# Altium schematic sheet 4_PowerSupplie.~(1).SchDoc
size 414 x 293 mm; SheetNumber: 4; SheetTotal: 4; PageSetup: Record=PageOptionsZCenterHorizontal=TrueZCenterVertical=TrueZPrintScale=1.00ZXCorrection=0.00ZYCorrection=0.00ZPrintKind=1ZBorderSize=5000000ZLeftOffset=0ZBottomOffset=0ZOrientation=2ZPaperLength=1000ZPaperWidth=1000ZScale=100ZPaperSource=7ZPrintQuality=-4ZMediaType=1ZDitherType=10ZPaperKind=A3ZPrintScaleMode=0; Razrabotal: {Разработал}; Proveril: {Проверил}; Tkontr: {Т.контр.}; Nkontr: {Н.контр.}; Ytverdil: {Утвердил}; Nazvanie1: {Название1}; Nazvanie2: {Название2}; Oboznachenie: {Обозначение}
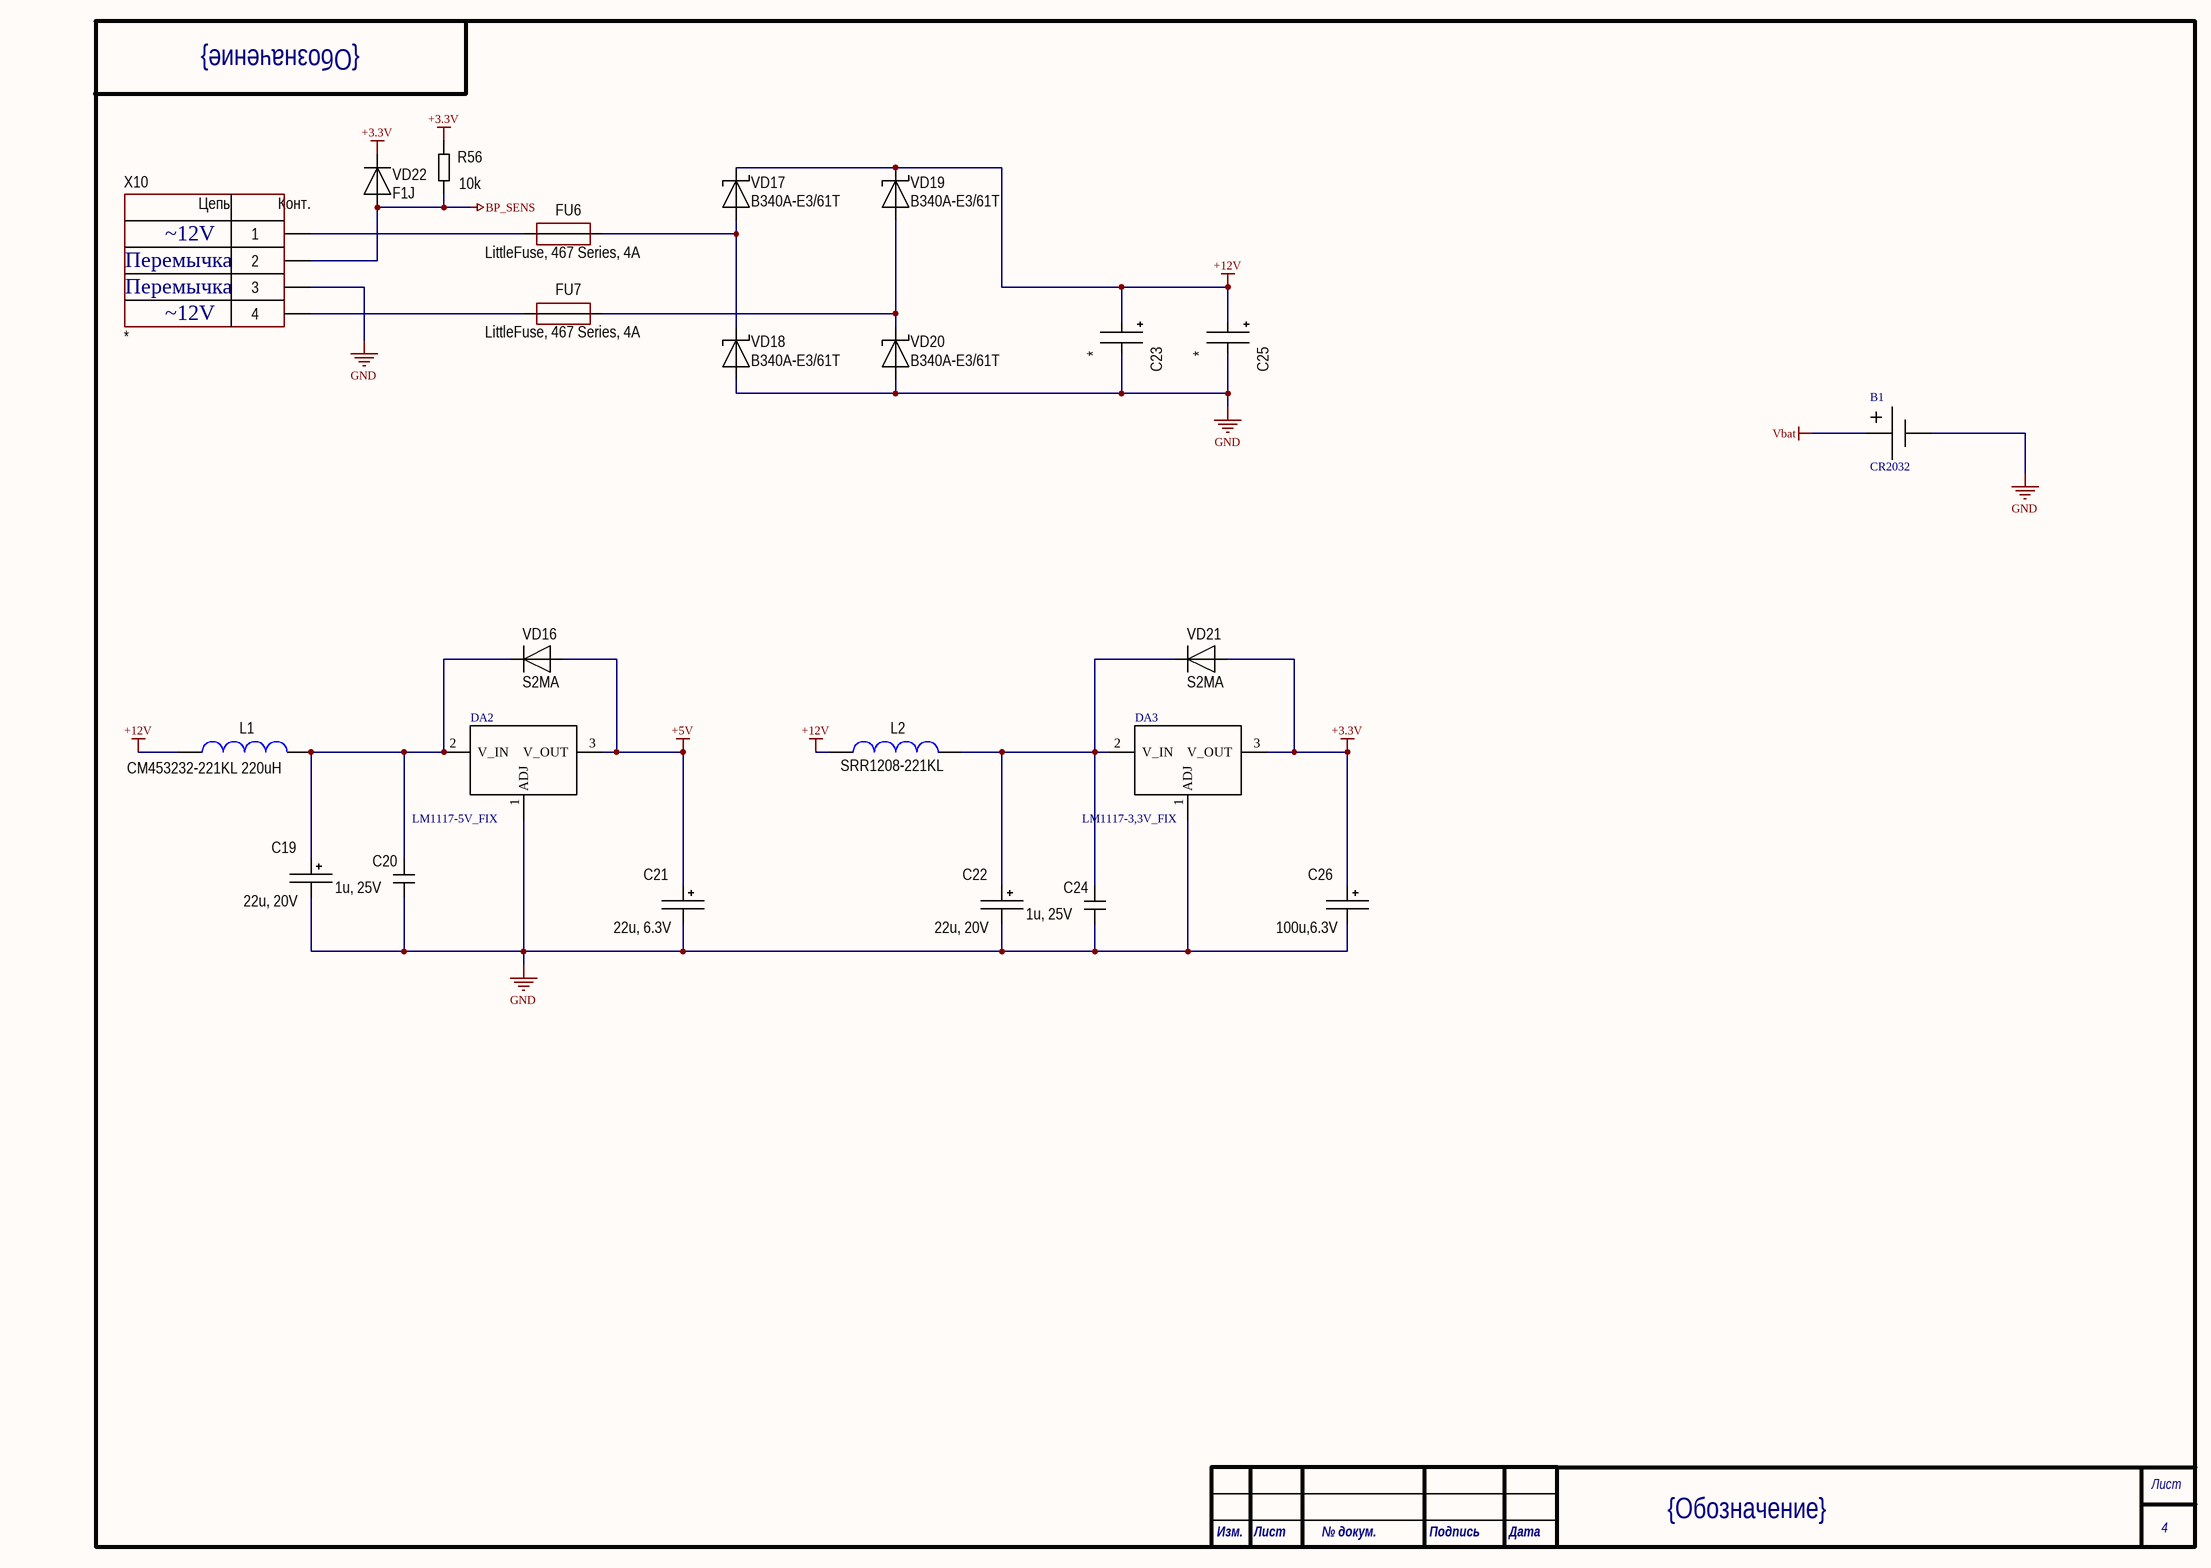
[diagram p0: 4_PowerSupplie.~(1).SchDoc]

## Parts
B1  CR2032  [CR2032]
C19  22u, 20V  [TANTAL_B]
C20  1u, 25V  [CH0805C]
C21  22u, 6.3V  [TANTAL_B]
C22  22u, 20V  [TANTAL_B]
C23  *  [D10C4.4H10]
C24  1u, 25V  [CH0805C]
C25  *  [D10C4.4H10]
C26  100u,6.3V  [TANTAL_B]
DA2  LM1117-5V_FIX  [SOT223_123]
DA3  LM1117-3,3V_FIX  [SOT223_123]
FU6  LittleFuse, 467 Series, 4A  [CH0603F]
FU7  LittleFuse, 467 Series, 4A  [CH0603F]
L1  CM453232-221KL 220uH  [IND:1812]
L2  SRR1208-221KL  [IND: SRR1208]
R56  10k  [CH0805R]
VD16  S2MA  [SMA]
VD17  B340A-E3/61T  [SMA]
VD18  B340A-E3/61T  [SMA]
VD19  B340A-E3/61T  [SMA]
VD20  B340A-E3/61T  [SMA]
VD21  S2MA  [SMA]
VD22  F1J  [SOD123F]
X10  *  [CON: CWF-4]

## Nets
+3.3V: C26.1 DA3.3(V_OUT) R56.2 VD21.1 VD22.2
+5V: C21.1 DA2.3(V_OUT) VD16.1
+12V: C23.1 C25.1 L1.2 L2.2 VD17.2 VD19.2
BP_SENS: R56.1 VD22.1 X10.2
GND: B1.2 C19.2 C20.1 C21.2 C22.2 C23.2 C24.1 C25.2 C26.2 DA2.1(ADJ) DA3.1(ADJ) VD18.1 VD20.1 X10.3
Vbat: B1.1
NetC19_1: C19.1 C20.2 DA2.2(V_IN) L1.1 VD16.2
NetC22_1: C22.1 C24.2 DA3.2(V_IN) L2.1 VD21.2
NetFU6_1: FU6.1 X10.1
NetFU6_2: FU6.2 VD17.1 VD18.2
NetFU7_1: FU7.1 X10.4
NetFU7_2: FU7.2 VD19.1 VD20.2

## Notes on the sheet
- Перемычка
- 2V

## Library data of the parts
B1 = Battery_CR2032
C19 C21 C22 C26 = TantalCap
C20 C24 = Capacitor
C23 C25 = AlumCap
DA2 DA3 = LM1117
FU6 FU7 = Fuse
L1 L2 = Inductor
R56 = Resistor
VD16 VD21 VD22 = Diod
VD17-VD20 = Diod Schottky
X10 = 4-Connector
